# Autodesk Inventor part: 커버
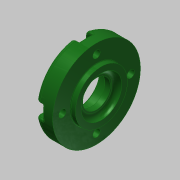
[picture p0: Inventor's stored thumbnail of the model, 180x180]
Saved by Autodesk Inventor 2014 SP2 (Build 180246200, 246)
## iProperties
Created: 2015-11
Part Number: 커버
Material: 알루미늄 6061
Document SubType Name: Modeling
Designer: mduedu
Density: 1 g/cm^3
Appearance: 매끄러움 - 짙은 산림 녹색
Author: mduedu
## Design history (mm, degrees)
sketch "스케치1"
  geometry: L1 (-7, 0)-(7, 0); L2 (-7, 0)-(-7, 27); L3 (-7, 27)-(4, 27); L4 (4, 27)-(4, 16); L5 (4, 16)-(7, 16); L6 (7, 16)-(7, 0); 2 further points
  constraints: 12 end point, 3 perpendicular, 2 parallel, 1 coincident, 1 horizontal, 1 midpoint
  dimensions: "d0" = 14 distance of L1.start L1.end; "d1" = 54 diameter of L3 L1; "d2" = 3 distance of L4.end L5.end; "d3" = 32 diameter of L5 L1
revolve "회전1" sketch "스케치1" stored, may be unused: angle "d4" = 90 deg
hole "구멍1" diameter "d7" = 25; stored, may be unused: countersink angle "d11" = 90 deg, drill point angle "d13" = 0 deg; dims "d5" = 10, "d6" = 10, "d8" = 6, "d9" = 4, "d10" = 2, "d12" = 3
hole "구멍2" diameter "d16" = 25; stored, may be unused: countersink angle "d20" = 90 deg, drill point angle "d22" = 0 deg; dims "d17" = 6, "d18" = 4, "d19" = 2, "d21" = 7.7, "d58" = 10, "d59" = 10
hole "구멍3" diameter "d25" = 17; stored, may be unused: countersink angle "d29" = 90 deg, drill point angle "d31" = 0 deg; dims "d23" = 10, "d24" = 10, "d26" = 6, "d27" = 4, "d28" = 2, "d30" = 4.2
chamfer "모따기1" distance "d32" = 0.6; stored, may be unused: second distance "d33" = 2, angle "d34" = 30 deg
fillet "모깎기1" dims "d35" = 0.3
fillet "모깎기2" dims "d36" = 3
fillet "모깎기3" dims "d37" = 3
fillet "모깎기4" dims "d38" = 0.3
sketch "스케치3" dims "d61" = 42
  geometry: C1 r 27 at (0, 0) reference; 2 further points
  constraints: 2 vertical alignment, 1 coincident, 2 other
hole "구멍4" sketch "스케치3" at (0, 21) diameter "d44" = 4.5; stored, may be unused: countersink angle "d48" = 90 deg, drill point angle "d50" = 0 deg; dims "d45" = 6, "d46" = 8, "d47" = 4.6, "d49" = 8
sketch "스케치4"
  geometry: L1 (-4, 5.702)-(-4, 0); L2 (4, 5.702)-(4, 0); A1 r 27 centre (0, -21) between (-4, 5.702) and (4, 5.702) reference; A2 r 4 centre (0, 0) between (-2.824, 2.833) and (2.824, 2.833) reference
  constraints: 4 end point, 4 point on circle, 2 tangent, 2 vertical
extrude "돌출1" cut sketch "스케치4" stored distance "d51" = 0; taper "d52" = 0 deg
fillet "모깎기5" dims "d56" = 0.3
fillet "모깎기6" dims "d57" = 1
node "솔리드1"
pattern_circular "원형 패턴2" dims angle "d64" = 360 deg
pattern_circular "원형 패턴1" dims angle "d54" = 360 deg
